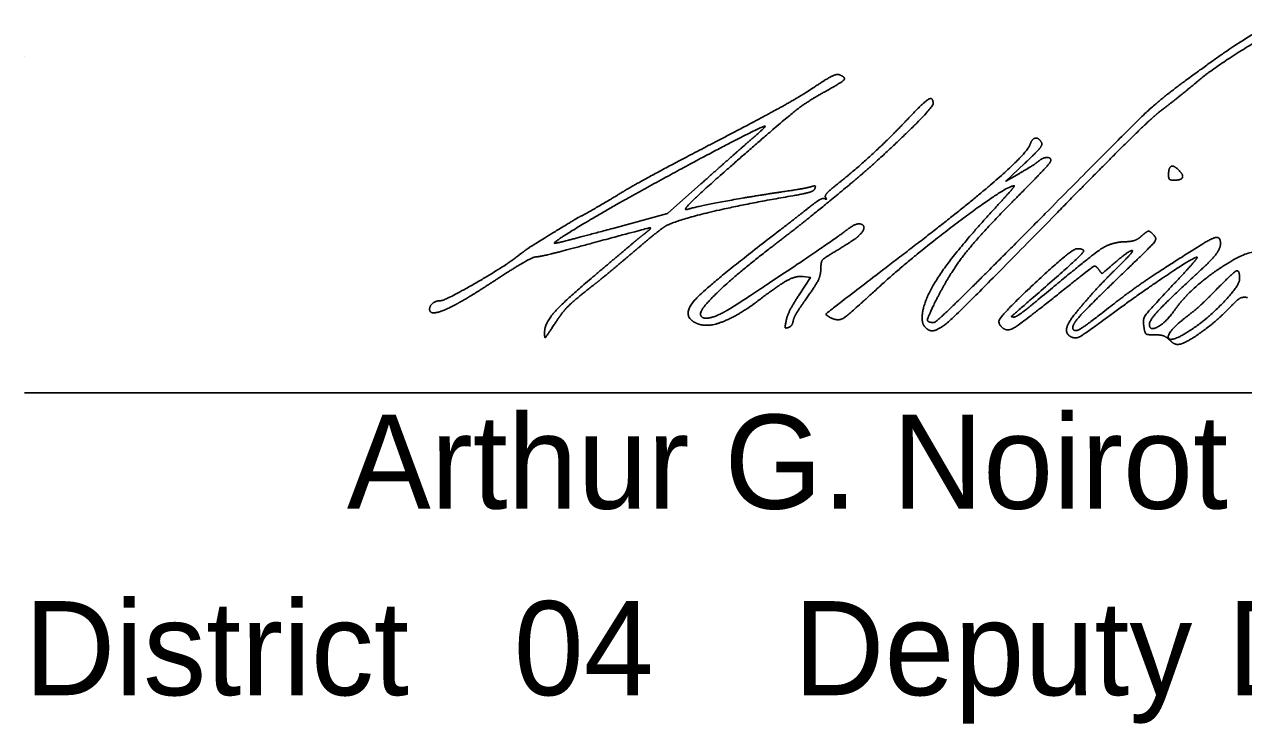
# Model space of a CAD drawing. Extents: x 0 to 36.9, y 0 to 22.
# Drawn here: x 24.495 to 26.309, y 8.315 to 9.355 of the extents above; entities that cross this region are included whole.
import ezdxf

# ---------------------------------------------------------------- set-up
doc = ezdxf.new("R2010")
doc.units = 0
doc.layers.add('SH_Data', color=7, linetype='Continuous')
doc.layers.add('SH_Text', color=7, linetype='Continuous')

msp = doc.modelspace()

# ---------------------------------------------------------------- linework, layer by layer
at = {"layer": 'SH_Data'}
for p, q in [((24.4955, 9.307), (24.4955, 9.307)), ((24.4955, 8.807), (27.9955, 8.807))]:
    msp.add_line(p, q, dxfattribs=at)
at = {"layer": 'SH_Text'}
for points in [[(25.9757, 9.1333), (25.9553, 9.1218), (25.9835, 9.1481)], [(25.5019, 9.1176), (25.4524, 9.0735), (25.3709, 9.0515)], [(25.6541, 8.9798), (25.6648, 8.9785), (25.648, 8.9527)]]:
    msp.add_lwpolyline(points, dxfattribs=at)
for points in [[(26.3721, 9.3549), (26.3508, 9.3557), (26.2942, 9.324), (26.2228, 9.2713)], [(26.2446, 9.2734), (26.262, 9.288), (26.3372, 9.3358), (26.3575, 9.345)], [(25.7076, 9.2801), (25.704, 9.2815), (25.6884, 9.2737), (25.6701, 9.2613)], [(25.6863, 9.2547), (25.7116, 9.2687), (25.7179, 9.2762), (25.7076, 9.2801)], [(26.2228, 9.2713), (26.1844, 9.243), (26.144, 9.2047), (26.0143, 9.0737)], [(26.1824, 9.2234), (26.2048, 9.2408), (26.2318, 9.2625), (26.2446, 9.2734)], [(25.6701, 9.2613), (25.6528, 9.2497), (25.6018, 9.221), (25.5568, 9.1975)], [(25.5639, 9.1593), (25.6286, 9.2157), (25.6606, 9.2406), (25.6863, 9.2547)], [(25.7228, 9.1164), (25.7606, 9.1476), (25.8474, 9.2315), (25.8474, 9.2369)], [(25.8474, 9.2369), (25.8474, 9.2477), (25.8328, 9.2388), (25.8096, 9.2141)], [(26.0303, 9.0731), (26.1029, 9.1472), (26.1713, 9.2148), (26.1824, 9.2234)], [(25.5568, 9.1975), (25.4808, 9.158), (25.4017, 9.1156), (25.3873, 9.1068)], [(25.3933, 9.0964), (25.4703, 9.1392), (25.5958, 9.2051), (25.5974, 9.2035)], [(25.5974, 9.2035), (25.5979, 9.2029), (25.5878, 9.1933), (25.5749, 9.1821)], [(25.8096, 9.2141), (25.7844, 9.1871), (25.7285, 9.1357), (25.6999, 9.1133)], [(25.5749, 9.1821), (25.562, 9.1709), (25.5291, 9.1419), (25.5019, 9.1176)], [(25.9835, 9.1481), (26.0011, 9.1645), (26.0106, 9.1763), (26.0087, 9.1793)], [(26.0087, 9.1793), (26.0043, 9.1865), (25.9949, 9.1852), (25.9919, 9.177)], [(25.9919, 9.177), (25.9867, 9.1628), (25.8928, 9.0815), (25.7981, 9.0091)], [(25.4819, 9.0797), (25.4734, 9.077), (25.5091, 9.1116), (25.5639, 9.1593)], [(25.9745, 9.1003), (26.0009, 9.1269), (26.0225, 9.1502), (26.0225, 9.1522)], [(26.0025, 9.1502), (25.9989, 9.1472), (25.9869, 9.1396), (25.9757, 9.1333)], [(26.0225, 9.1522), (26.0225, 9.1575), (26.0096, 9.1563), (26.0025, 9.1502)], [(26.2127, 9.1382), (26.2053, 9.1456), (26.1976, 9.1419), (26.1976, 9.131)], [(26.1976, 9.131), (26.1976, 9.1259), (26.2004, 9.1231), (26.2055, 9.1231)], [(26.2055, 9.1231), (26.2164, 9.1231), (26.2201, 9.1308), (26.2127, 9.1382)], [(25.3873, 9.1068), (25.3704, 9.0963), (25.3253, 9.0701), (25.3243, 9.0701)], [(25.6031, 9.0207), (25.6421, 9.0506), (25.6697, 9.0727), (25.7228, 9.1164)], [(25.6657, 9.1134), (25.6615, 9.1121), (25.6397, 9.1083), (25.6172, 9.105)], [(25.6385, 9.0999), (25.6565, 9.103), (25.6705, 9.1075), (25.6715, 9.1105)], [(25.6715, 9.1105), (25.6727, 9.1141), (25.6708, 9.115), (25.6657, 9.1134)], [(25.6999, 9.1133), (25.6916, 9.1068), (25.686, 9.0996), (25.6874, 9.0974)], [(25.7655, 8.963), (25.8167, 9.0099), (25.9567, 9.1149), (25.968, 9.1149)], [(25.968, 9.1149), (25.9692, 9.1149), (25.9571, 9.1007), (25.9411, 9.0834)], [(25.2845, 9.0294), (25.2801, 9.0294), (25.3464, 9.0702), (25.3933, 9.0964)], [(25.4464, 9.053), (25.4582, 9.0616), (25.5634, 9.0872), (25.6385, 9.0999)], [(25.6172, 9.105), (25.5738, 9.0985), (25.4937, 9.0836), (25.4819, 9.0797)], [(25.686, 9.0957), (25.6839, 9.097), (25.6731, 9.0909), (25.662, 9.082)], [(25.6874, 9.0974), (25.6888, 9.0952), (25.6882, 9.0944), (25.686, 9.0957)], [(25.853, 8.9469), (25.8726, 8.9859), (25.9184, 9.0437), (25.9745, 9.1003)], [(25.3243, 9.0701), (25.3237, 9.0701), (25.3134, 9.0641), (25.3013, 9.0567)], [(25.662, 9.082), (25.6509, 9.0732), (25.6317, 9.0583), (25.6194, 9.0488)], [(25.9411, 9.0834), (25.8821, 9.0195), (25.8311, 8.943), (25.8311, 8.9184)], [(25.846, 8.8991), (25.8564, 8.8991), (25.9018, 8.9421), (26.0303, 9.0731)], [(26.0143, 9.0737), (25.9259, 8.9843), (25.8513, 8.9112), (25.8487, 8.9113)], [(25.3013, 9.0567), (25.25, 9.0252), (25.2425, 9.0203), (25.2263, 9.0079)], [(25.3709, 9.0515), (25.3261, 9.0394), (25.2872, 9.0294), (25.2845, 9.0294)], [(25.3397, 9.0294), (25.4205, 9.0513), (25.4308, 9.0532), (25.4179, 9.0434)], [(25.398, 9.0134), (25.4179, 9.0304), (25.4397, 9.0482), (25.4464, 9.053)], [(25.7365, 9.0402), (25.7491, 9.0525), (25.7349, 9.0614), (25.7204, 9.0502)], [(25.4179, 9.0434), (25.4134, 9.04), (25.4061, 9.0341), (25.4016, 9.0302)], [(25.6194, 9.0488), (25.5146, 8.9685), (25.4724, 8.9225), (25.4932, 8.9114)], [(25.7204, 9.0502), (25.7018, 9.0358), (25.5479, 8.9328), (25.5351, 8.9262)], [(25.7059, 9.0198), (25.7199, 9.0283), (25.7337, 9.0374), (25.7365, 9.0402)], [(26.1292, 8.9841), (26.1712, 9.0246), (26.1806, 9.0355), (26.1768, 9.0401)], [(26.156, 9.0388), (26.1518, 9.0351), (26.1416, 9.0318), (26.1333, 9.0316)], [(26.1768, 9.0401), (26.1706, 9.0475), (26.1652, 9.0472), (26.156, 9.0388)], [(26.2749, 9.0285), (26.275, 9.0378), (26.2642, 9.0382), (26.2501, 9.0294)], [(25.257, 9.0091), (25.2612, 9.0091), (25.2984, 9.0182), (25.3397, 9.0294)], [(25.4016, 9.0302), (25.3971, 9.0264), (25.3712, 9.0045), (25.344, 8.9816)], [(25.5013, 8.9246), (25.5013, 8.9324), (25.5595, 8.9873), (25.6031, 9.0207)], [(25.6805, 8.9943), (25.6805, 9.0023), (25.6857, 9.0076), (25.7059, 9.0198)], [(26.0608, 9.0213), (26.0537, 9.0213), (25.9452, 8.9199), (25.9452, 8.9132)], [(26.1333, 9.0316), (26.1127, 9.0312), (26.0812, 9.0102), (26.0005, 8.9429)], [(26.0279, 8.9764), (26.0659, 9.0096), (26.0744, 9.0213), (26.0608, 9.0213)], [(26.1124, 8.9958), (26.1386, 9.0186), (26.1476, 9.0187), (26.1243, 8.9959)], [(26.2501, 9.0294), (26.1942, 8.9945), (26.1409, 8.9586), (26.1144, 8.9378)], [(26.3343, 9.0156), (26.3182, 9.0218), (26.2295, 8.9622), (26.2068, 8.9301)], [(26.2364, 8.9809), (26.2597, 9.0024), (26.2748, 9.0211), (26.2749, 9.0285)], [(25.2263, 9.0079), (25.207, 8.9932), (25.1211, 8.9439), (25.1147, 8.9439)], [(25.2024, 8.9785), (25.2282, 8.9953), (25.2528, 9.0091), (25.257, 9.0091)], [(25.3431, 8.9679), (25.3534, 8.976), (25.3782, 8.9965), (25.398, 9.0134)], [(25.7981, 9.0091), (25.6927, 8.9286), (25.6856, 8.922), (25.6985, 8.917)], [(26.1176, 8.9273), (26.1614, 8.9595), (26.2383, 9.0105), (26.2402, 9.0084)], [(26.2402, 9.0084), (26.241, 9.0077), (26.2243, 8.9887), (26.2032, 8.9663)], [(25.1364, 8.9378), (25.1469, 8.9433), (25.1766, 8.9616), (25.2024, 8.9785)], [(25.344, 8.9816), (25.2986, 8.9434), (25.2693, 8.91), (25.2693, 8.8964)], [(25.5868, 8.9436), (25.6174, 8.9671), (25.6435, 8.9811), (25.6541, 8.9798)], [(25.6541, 8.9404), (25.6726, 8.9663), (25.6805, 8.9824), (25.6805, 8.9943)], [(26.0369, 8.9564), (26.083, 8.9932), (26.0889, 8.9967), (26.0934, 8.9906)], [(26.0563, 8.9006), (26.0518, 8.9051), (26.0767, 8.9337), (26.1292, 8.9841)], [(26.1243, 8.9959), (26.1029, 8.9749), (26.0798, 8.9499), (26.0602, 8.9265)], [(26.0934, 8.9906), (26.098, 8.9842), (26.0996, 8.9847), (26.1124, 8.9958)], [(26.1691, 8.9092), (26.1691, 8.9148), (26.1975, 8.9451), (26.2364, 8.9809)], [(26.2683, 8.96), (26.2933, 8.9857), (26.3034, 8.9904), (26.3034, 8.9763)], [(25.2836, 8.9083), (25.2957, 8.927), (25.3134, 8.9446), (25.3431, 8.9679)], [(25.6985, 8.917), (25.7078, 8.9135), (25.7223, 8.9234), (25.7655, 8.963)], [(25.9679, 8.9196), (25.9632, 8.9197), (25.9646, 8.9211), (26.0279, 8.9764)], [(26.2032, 8.9663), (26.1656, 8.9264), (26.1587, 8.9155), (26.1617, 8.9005)], [(26.3034, 8.9763), (26.3034, 8.9668), (26.257, 8.9178), (26.2326, 8.9016)], [(25.1147, 8.9439), (25.1077, 8.9439), (25.0983, 8.9364), (25.0983, 8.9309)], [(25.5118, 8.9073), (25.5243, 8.9073), (25.5656, 8.9273), (25.5868, 8.9436)], [(25.648, 8.9527), (25.6388, 8.9384), (25.6301, 8.9212), (25.6288, 8.9145)], [(25.8487, 8.9113), (25.8384, 8.9115), (25.8395, 8.9201), (25.853, 8.9469)], [(25.9498, 8.9043), (25.957, 8.897), (25.9788, 8.9101), (26.0369, 8.9564)], [(26.0005, 8.9429), (25.985, 8.93), (25.9704, 8.9196), (25.9679, 8.9196)], [(26.225, 8.9204), (26.2357, 8.9286), (26.2552, 8.9464), (26.2683, 8.96)], [(26.2866, 8.9316), (26.3001, 8.9454), (26.3071, 8.9496), (26.3151, 8.9487)], [(25.0983, 8.9309), (25.0983, 8.9244), (25.1179, 8.9279), (25.1364, 8.9378)], [(25.5351, 8.9262), (25.5197, 8.9183), (25.5013, 8.9174), (25.5013, 8.9246)], [(25.6392, 8.9137), (25.64, 8.918), (25.6467, 8.93), (25.6541, 8.9404)], [(26.0602, 8.9265), (26.0484, 8.9123), (26.0441, 8.8953), (26.0512, 8.8909)], [(26.0512, 8.8909), (26.0585, 8.8864), (26.0729, 8.8943), (26.1176, 8.9273)], [(26.1144, 8.9378), (26.0764, 8.9082), (26.0595, 8.8974), (26.0563, 8.9006)], [(26.2068, 8.9301), (26.194, 8.9118), (26.1691, 8.8981), (26.1691, 8.9092)], [(26.2113, 8.8788), (26.2203, 8.8788), (26.2672, 8.9116), (26.2866, 8.9316)], [(25.2693, 8.8964), (25.2693, 8.8879), (25.2715, 8.8898), (25.2836, 8.9083)], [(25.4932, 8.9114), (25.4974, 8.9091), (25.5057, 8.9073), (25.5118, 8.9073)], [(25.6288, 8.9145), (25.6269, 8.905), (25.6276, 8.9026), (25.632, 8.904)], [(25.632, 8.904), (25.6352, 8.9051), (25.6384, 8.9094), (25.6392, 8.9137)], [(25.8311, 8.9184), (25.8311, 8.9132), (25.8333, 8.9067), (25.836, 8.904)], [(25.9452, 8.9132), (25.9452, 8.9108), (25.9472, 8.9068), (25.9498, 8.9043)], [(26.2326, 8.9016), (26.2008, 8.8804), (26.1942, 8.8968), (26.225, 8.9204)], [(25.836, 8.904), (25.8387, 8.9013), (25.8432, 8.8991), (25.846, 8.8991)], [(26.1617, 8.9005), (26.1628, 8.895), (26.1668, 8.8931), (26.1772, 8.8931)], [(26.1772, 8.8931), (26.1853, 8.8932), (26.1943, 8.8902), (26.1985, 8.886)], [(26.1985, 8.886), (26.2025, 8.882), (26.2082, 8.8788), (26.2113, 8.8788)]]:
    msp.add_open_spline(points, degree=2, dxfattribs=at)

# ---------------------------------------------------------------- texts
for s, p in [('Arthur G. Noirot Jr., P.E.', (24.9752, 8.6344)), ('District   04    Deputy Director', (24.4955, 8.357))]:
    msp.add_text(s, height=0.14, dxfattribs=at).set_placement(p)

doc.saveas('drawing.dxf')
